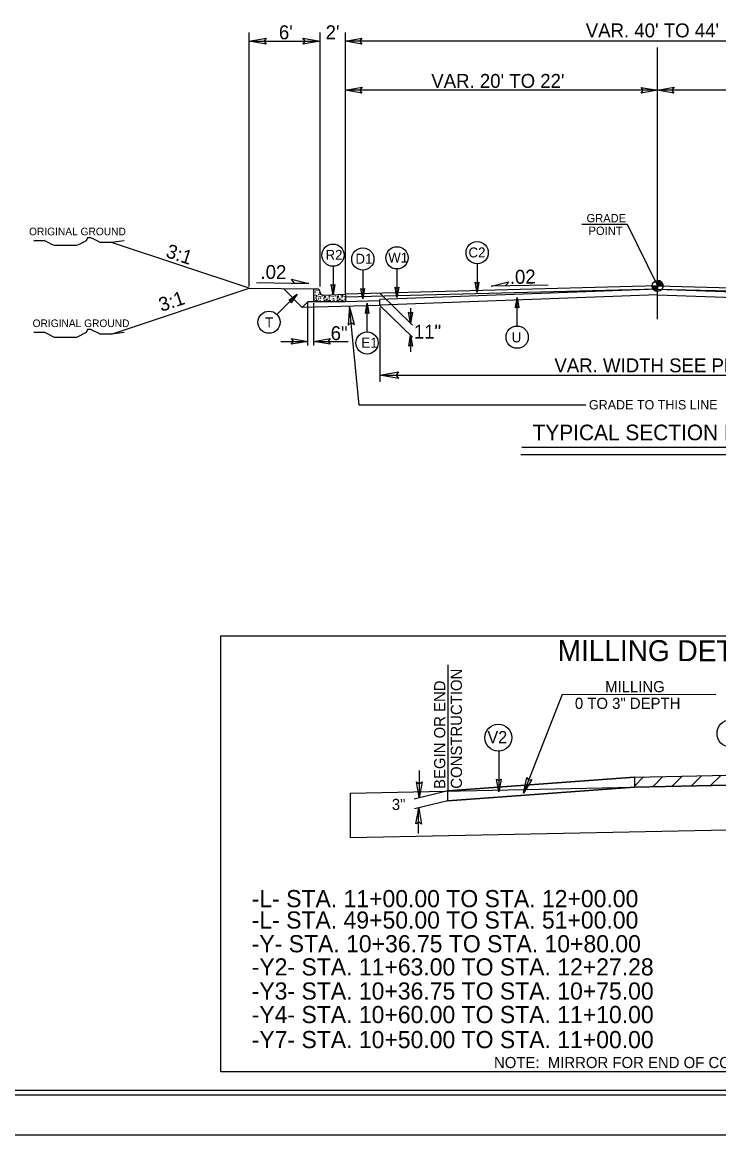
# Model space of a CAD drawing. Extents: x 957297 to 961629, y 830661 to 840840.
# Drawn here: x 959081 to 959472, y 830661 to 831285 of the extents above; entities that cross this region are included whole.
import ezdxf

# ---------------------------------------------------------------- set-up
doc = ezdxf.new("R2010")
doc.units = 0
for name, color, linetype in [('Default', 7, 'Continuous'), ('Old_Level_1', 7, 'Continuous'), ('Old_Level_11', 7, 'Continuous'), ('Old_Level_21', 7, 'Continuous'), ('Old_Level_3', 7, 'Continuous'), ('Prop Dimension', 7, 'Continuous'), ('Prop Dimension Text', 7, 'Continuous'), ('Sheet Plot Border Inside CELL', 7, 'Continuous'), ('Sheet Plot Border Outside CELL', 7, 'Continuous'), ('Sheet Typical CELL', 7, 'Continuous'), ('Typical ID Circle CELL', 7, 'Continuous'), ('Typical Pavement Slope CELL', 7, 'Continuous'), ('Typical Terminator CELL', 7, 'Continuous'), ('Typical Text Grade Point CELL', 7, 'Continuous'), ('Typical Text ID Circle CELL', 7, 'Continuous')]:
    doc.layers.add(name, color=color, linetype=linetype)

msp = doc.modelspace()

# ---------------------------------------------------------------- linework, layer by layer
at = {"layer": 'Default'}
msp.add_line((959437.72, 831118.14), (959437.72, 831270.38), dxfattribs=at)
at = {"layer": 'Old_Level_1'}
for p, q in [((959208.65, 831136.31), (959208.65, 831278.82)), ((959248.48, 831136.31), (959248.48, 831278.82)), ((959262.72, 831132.16), (959262.72, 831278.82)), ((959208.65, 831273.95), (959248.48, 831273.95)), ((959612.72, 831273.95), (959262.72, 831273.95)), ((959437.72, 831246.46), (959262.72, 831246.46)), ((959612.72, 831246.46), (959437.72, 831246.46)), ((959208.65, 831135.37), (959131.47, 831161.1)), ((959212.89, 831138.59), (959242.11, 831138)), ((959437.72, 831136.71), (959437.72, 831139.78)), ((959131.47, 831109.64), (959208.65, 831135.37)), ((959208.65, 831135.37), (959244.92, 831135.01)), ((959238.5, 831124.7), (959228.03, 831135.18)), ((959437.72, 831136.71), (959262.72, 831132.16)), ((959437.72, 831134.98), (959262.72, 831130.43)), ((959437.72, 831134.98), (959281.92, 831129.06)), ((959281.92, 831132.66), (959300.39, 831114.73)), ((959437.68, 831131.79), (959281.92, 831125.88)), ((959376.37, 831137.18), (959344.4, 831136.54)), ((959434.66, 831136.71), (959437.72, 831136.71)), ((959437.68, 831131.79), (959593.52, 831125.87)), ((959437.72, 831136.71), (959612.72, 831132.16)), ((959440.78, 831136.71), (959437.72, 831136.71)), ((959437.72, 831133.66), (959437.72, 831136.71)), ((959437.72, 831136.71), (959437.72, 831133.66)), ((959437.72, 831136.71), (959437.72, 831134.98)), ((959437.72, 831134.98), (959612.72, 831130.43)), ((959437.72, 831134.98), (959593.52, 831129.06)), ((959241.62, 831127.82), (959238.5, 831124.7)), ((959281.92, 831125.83), (959238.5, 831124.7)), ((959244.92, 831127.88), (959241.62, 831127.82)), ((959241.62, 831103.33), (959241.62, 831127.37)), ((959244.92, 831103.33), (959244.92, 831127.08)), ((959281.92, 831128.38), (959262.72, 831127.88)), ((959270.46, 831069.9), (959264.98, 831125.39)), ((959281.92, 831125.88), (959281.92, 831129.06)), ((959281.92, 831125.83), (959281.92, 831125.88)), ((959281.92, 831125.83), (959300.39, 831107.9)), ((959281.92, 831124.68), (959281.92, 831083.02)), ((959299.18, 831124.26), (959299.18, 831115.9)), ((959299.25, 831109.01), (959299.25, 831099.79)), ((959226.42, 831105.62), (959241.62, 831105.62)), ((959244.92, 831105.62), (959264.18, 831105.62)), ((959281.92, 831086.71), (959593.52, 831086.71)), ((959397.52, 831069.9), (959270.46, 831069.9)), ((959361.6, 831046.32), (959529.29, 831046.32)), ((959361.04, 831042.2), (959528.74, 831042.2)), ((959424.73, 830856.17), (959429.87, 830861.32)), ((959435.01, 830855.85), (959440.7, 830861.54)), ((959445.84, 830856.07), (959451.53, 830861.77)), ((959456.67, 830856.3), (959462.37, 830861.99)), ((959467.5, 830856.52), (959473.2, 830862.22))]:
    msp.add_line(p, q, dxfattribs=at)
for points in [[(959437.76, 831139.78), (959437.76, 831139.78), (959437.76, 831136.71)], [(959437.81, 831139.78), (959437.81, 831136.71)], [(959437.87, 831139.77), (959437.87, 831136.71)], [(959437.94, 831139.76), (959437.94, 831136.71)], [(959438, 831139.76), (959438, 831136.71)], [(959438.06, 831139.76), (959438.06, 831136.71)], [(959438.12, 831139.75), (959438.12, 831136.71)], [(959438.18, 831139.75), (959438.18, 831136.71)], [(959438.23, 831139.72), (959438.23, 831136.71)], [(959438.3, 831139.72), (959438.3, 831136.71)], [(959438.36, 831139.71), (959438.36, 831136.71)], [(959438.42, 831139.69), (959438.42, 831136.71)], [(959438.49, 831139.67), (959438.49, 831136.71)], [(959438.55, 831139.66), (959438.55, 831136.71)], [(959438.61, 831139.64), (959438.61, 831136.71)], [(959438.67, 831139.62), (959438.67, 831136.71)], [(959438.74, 831139.6), (959438.73, 831136.71)], [(959438.79, 831139.58), (959438.79, 831136.71)], [(959438.85, 831139.56), (959438.85, 831136.71)], [(959438.92, 831139.53), (959438.92, 831136.71)], [(959438.98, 831139.51), (959438.98, 831136.71)], [(959439.04, 831139.47), (959439.04, 831136.71)], [(959439.09, 831139.45), (959439.09, 831136.71)], [(959439.15, 831139.43), (959439.15, 831136.71)], [(959439.21, 831139.39), (959439.21, 831136.71)], [(959439.28, 831139.35), (959439.28, 831136.71)], [(959439.34, 831139.31), (959439.34, 831136.71)], [(959439.4, 831139.27), (959439.4, 831136.71)], [(959439.47, 831139.22), (959439.47, 831136.71)], [(959439.52, 831139.19), (959439.52, 831136.71)], [(959439.59, 831139.14), (959439.59, 831136.71)], [(959439.65, 831139.09), (959439.65, 831136.71)], [(959439.71, 831139.05), (959439.71, 831136.71)], [(959439.77, 831138.99), (959439.77, 831136.71)], [(959439.83, 831138.93), (959439.83, 831136.71)], [(959439.9, 831138.87), (959439.9, 831136.71)], [(959439.95, 831138.8), (959439.95, 831136.71)], [(959440.01, 831138.74), (959440.01, 831136.71)], [(959440.07, 831138.68), (959440.07, 831136.71)], [(959440.13, 831138.58), (959440.13, 831136.71)], [(959440.2, 831138.51), (959440.2, 831136.71)], [(959440.26, 831138.43), (959440.26, 831136.71)], [(959440.32, 831138.33), (959440.32, 831136.71)], [(959440.38, 831138.23), (959440.38, 831136.71)], [(959440.44, 831138.12), (959440.44, 831136.71)], [(959440.5, 831137.98), (959440.5, 831136.71)], [(959440.57, 831137.83), (959440.57, 831136.71)], [(959440.63, 831137.67), (959440.63, 831136.71)], [(959440.69, 831137.46), (959440.69, 831136.71)], [(959434.68, 831136.71), (959434.68, 831136.39)], [(959434.74, 831136.71), (959434.74, 831136.03)], [(959434.8, 831136.71), (959434.8, 831135.8)], [(959434.86, 831136.71), (959434.86, 831135.62)], [(959434.93, 831136.71), (959434.93, 831135.48)], [(959434.99, 831136.71), (959434.99, 831135.35)], [(959435.05, 831136.71), (959435.05, 831135.24)], [(959435.11, 831136.71), (959435.11, 831135.12)], [(959435.17, 831136.71), (959435.17, 831135.04)], [(959435.23, 831136.71), (959435.23, 831134.95)], [(959435.3, 831136.71), (959435.3, 831134.86)], [(959435.36, 831136.71), (959435.36, 831134.79)], [(959435.42, 831136.71), (959435.42, 831134.72)], [(959435.47, 831136.71), (959435.47, 831134.64)], [(959435.53, 831136.71), (959435.53, 831134.57)], [(959435.6, 831136.71), (959435.6, 831134.52)], [(959435.66, 831136.71), (959435.66, 831134.47)], [(959435.72, 831136.71), (959435.72, 831134.41)], [(959435.78, 831136.71), (959435.78, 831134.36)], [(959435.85, 831136.71), (959435.85, 831134.3)], [(959435.9, 831136.71), (959435.9, 831134.26)], [(959435.96, 831136.71), (959435.96, 831134.22)], [(959436.02, 831136.71), (959436.02, 831134.18)], [(959436.09, 831136.71), (959436.09, 831134.13)], [(959436.15, 831136.71), (959436.15, 831134.09)], [(959436.21, 831136.71), (959436.21, 831134.05)], [(959436.28, 831136.71), (959436.28, 831134.02)], [(959436.33, 831136.71), (959436.33, 831134)], [(959436.39, 831136.71), (959436.39, 831133.97)], [(959436.46, 831136.71), (959436.46, 831133.93)], [(959436.52, 831136.71), (959436.52, 831133.91)], [(959436.58, 831136.71), (959436.58, 831133.88)], [(959436.64, 831136.71), (959436.64, 831133.86)], [(959436.7, 831136.71), (959436.7, 831133.84)], [(959436.75, 831136.71), (959436.75, 831133.82)], [(959436.82, 831136.71), (959436.82, 831133.8)], [(959436.88, 831136.71), (959436.88, 831133.78)], [(959436.94, 831136.71), (959436.94, 831133.76)], [(959437, 831136.71), (959437, 831133.75)], [(959437.07, 831136.71), (959437.07, 831133.73)], [(959437.13, 831136.71), (959437.13, 831133.72)], [(959437.19, 831136.71), (959437.19, 831133.72)], [(959437.25, 831136.71), (959437.25, 831133.7)], [(959437.31, 831136.71), (959437.31, 831133.68)], [(959437.38, 831136.71), (959437.38, 831133.68)], [(959437.44, 831136.71), (959437.44, 831133.68)], [(959437.5, 831136.71), (959437.5, 831133.66)], [(959437.56, 831136.71), (959437.56, 831133.66)], [(959437.61, 831136.71), (959437.61, 831133.66)], [(959437.67, 831136.71), (959437.67, 831133.66), (959437.67, 831133.66)], [(959440.75, 831137.16), (959440.75, 831136.71)]]:
    msp.add_lwpolyline(points, dxfattribs=at)
for points in [[(959192.77, 830940.53), (959740.5, 830940.53), (959740.5, 830695.87), (959192.77, 830695.87)], [(959320.22, 830853.46), (959424.71, 830861.21), (959424.73, 830855.63), (959320.22, 830847.89)]]:
    msp.add_lwpolyline(points, close=True, dxfattribs=at)
msp.add_circle((959437.72, 831136.72), 3.06, dxfattribs=at)
for start, end in [(359.99048, 89.99048), (179.99048, 269.99048)]:
    msp.add_arc((959437.72, 831136.72), 3.06, start, end, dxfattribs=at)
at = {"layer": 'Old_Level_11'}
for p, q in [((959234.11, 831138.16), (959232.38, 831140.42)), ((959232.38, 831140.42), (959242.11, 831138)), ((959242.11, 831138), (959234.11, 831138.16)), ((959344.4, 831136.54), (959354.15, 831138.96)), ((959354.15, 831138.96), (959352.42, 831136.7)), ((959352.42, 831136.7), (959344.4, 831136.54))]:
    msp.add_line(p, q, dxfattribs=at)
for points in [[(959218.26, 831272.3), (959208.65, 831273.95), (959218.31, 831275.66), (959217.09, 831273.95)], [(959238.87, 831275.61), (959248.48, 831273.95), (959238.81, 831272.23), (959240.04, 831273.95)], [(959267.84, 831115.05), (959264.98, 831125.39), (959264.16, 831114.63), (959265.89, 831116.15)], [(959292.49, 831084.89), (959281.92, 831086.71), (959292.55, 831088.59), (959291.2, 831086.71)]]:
    msp.add_lwpolyline(points, close=True, dxfattribs=at)
at = {"layer": 'Old_Level_21'}
for points in [[(959138.56, 831161.98), (959131.47, 831161.1), (959129.69, 831161.1), (959127.03, 831161.1), (959125.26, 831161.1), (959123.49, 831161.98), (959121.71, 831162.88), (959119.94, 831163.76), (959118.16, 831163.76), (959117.27, 831161.98), (959115.5, 831161.1), (959113.73, 831160.21), (959111.96, 831159.33), (959110.18, 831159.33), (959108.41, 831159.33), (959106.63, 831159.33), (959104.86, 831159.33), (959103.09, 831159.33), (959101.32, 831159.33), (959099.54, 831159.33), (959097.77, 831160.21), (959096, 831161.1), (959094.23, 831161.98), (959091.56, 831161.98), (959089.79, 831161.98), (959088.01, 831161.98)], [(959138.56, 831110.52), (959131.47, 831109.64), (959129.69, 831109.64), (959127.03, 831109.64), (959125.26, 831109.64), (959123.49, 831110.52), (959121.71, 831111.42), (959119.94, 831112.3), (959118.16, 831112.3), (959117.27, 831110.52), (959115.5, 831109.64), (959113.73, 831108.74), (959111.96, 831107.87), (959110.18, 831107.87), (959108.41, 831107.87), (959106.63, 831107.87), (959104.86, 831107.87), (959103.09, 831107.87), (959101.32, 831107.87), (959099.54, 831107.87), (959097.77, 831108.74), (959096, 831109.64), (959094.23, 831110.52), (959091.56, 831110.52), (959089.79, 831110.52), (959088.01, 831110.52)]]:
    msp.add_lwpolyline(points, dxfattribs=at)
at = {"layer": 'Old_Level_3'}
for p, q in [((959244.92, 831131.44), (959244.92, 831134.7)), ((959244.92, 831127.88), (959244.92, 831131.44)), ((959245.23, 831135.01), (959246.7, 831135.01)), ((959246.28, 831131.19), (959246.28, 831130.57)), ((959246.91, 831131.16), (959246.28, 831131.19)), ((959246.28, 831130.57), (959246.91, 831131.16)), ((959248.62, 831132.81), (959248.5, 831132.65)), ((959248.5, 831132.65), (959248.66, 831132.69)), ((959250.32, 831131.54), (959262.72, 831132.16)), ((959250.32, 831131.54), (959250.32, 831131.54)), ((959253.51, 831131.19), (959253.51, 831130.57)), ((959254.14, 831131.16), (959253.51, 831131.19)), ((959253.51, 831130.57), (959254.14, 831131.16)), ((959260.74, 831131.19), (959260.74, 831130.57)), ((959261.37, 831131.16), (959260.74, 831131.19)), ((959260.74, 831130.57), (959261.37, 831131.16)), ((959262.72, 831132.16), (959262.72, 831127.88)), ((959262.72, 831127.88), (959244.92, 831127.88)), ((959246.19, 831128.29), (959246.69, 831128.99)), ((959246.88, 831128.33), (959246.19, 831128.29)), ((959246.69, 831128.99), (959246.88, 831128.33)), ((959250.61, 831128), (959250.98, 831128.66)), ((959251.58, 831128.23), (959250.61, 831128)), ((959250.82, 831130.76), (959250.92, 831130.24)), ((959251.71, 831130.51), (959250.82, 831130.76)), ((959250.92, 831130.24), (959251.71, 831130.51)), ((959250.98, 831128.66), (959251.58, 831128.23)), ((959253.42, 831128.29), (959253.92, 831128.99)), ((959254.11, 831128.33), (959253.42, 831128.29)), ((959253.92, 831128.99), (959254.11, 831128.33)), ((959257.84, 831128), (959258.21, 831128.66)), ((959258.81, 831128.23), (959257.84, 831128)), ((959258.04, 831130.76), (959258.15, 831130.24)), ((959258.94, 831130.51), (959258.04, 831130.76)), ((959258.15, 831130.24), (959258.94, 831130.51)), ((959258.21, 831128.66), (959258.81, 831128.23)), ((959260.65, 831128.29), (959261.14, 831128.99)), ((959261.34, 831128.33), (959260.65, 831128.29)), ((959261.14, 831128.99), (959261.34, 831128.33))]:
    msp.add_line(p, q, dxfattribs=at)
for centre in [(959244.98, 831133.15), (959245.66, 831131.66), (959245.79, 831133.05), (959245.96, 831133.84), (959246.88, 831134.24), (959247.05, 831133.25), (959247.74, 831131.86), (959248.07, 831134.1), (959248.11, 831132.72), (959248.93, 831131.82), (959249.99, 831131.16), (959251.54, 831131), (959257.22, 831131.16), (959258.77, 831131), (959260.12, 831131.66), (959262.2, 831131.86), (959245.08, 831130.37), (959245.11, 831128.03), (959245.2, 831129.22), (959245.66, 831128.3), (959245.83, 831129.94), (959246.39, 831129.45), (959246.65, 831130.04), (959247.51, 831129.68), (959247.68, 831129.09), (959248.04, 831130.67), (959248.54, 831128.59), (959248.7, 831129.59), (959248.8, 831129.88), (959248.83, 831130.73), (959249.26, 831128.76), (959250.29, 831129.71), (959250.98, 831129.42), (959252.01, 831128.86), (959252.11, 831129.42), (959252.3, 831130.37), (959252.34, 831128.03), (959252.43, 831129.22), (959252.89, 831128.3), (959253.06, 831129.94), (959253.62, 831129.45), (959253.88, 831130.04), (959254.74, 831129.68), (959254.91, 831129.09), (959255.27, 831130.67), (959255.76, 831128.59), (959255.93, 831129.59), (959256.03, 831129.88), (959256.06, 831130.73), (959256.49, 831128.76), (959257.52, 831129.71), (959258.21, 831129.42), (959259.23, 831128.86), (959259.33, 831129.42), (959259.53, 831130.37), (959259.56, 831128.03), (959259.65, 831129.22), (959260.12, 831128.3), (959260.28, 831129.94), (959260.84, 831129.45), (959261.11, 831130.04), (959261.97, 831129.68), (959262.13, 831129.09), (959262.5, 831130.67)]:
    msp.add_circle(centre, 0.0464, dxfattribs=at)
for centre, radius, start, end in [((959245.23, 831134.7), 0.309, 90, 180), ((959245.11, 831134.93), 0.0464, 259.65309, 10.34691), ((959246.7, 831133.23), 1.78, 1.07335, 90), ((959250.23, 831133.3), 1.76, 181.07335, 272.86241), ((959252.89, 831131.66), 0.0464, 167.77954, 17.93798), ((959256.16, 831131.82), 0.0464, 169.83737, 15.88014), ((959244.88, 831129.42), 0.0464, 330.41727, 29.58272)]:
    msp.add_arc(centre, radius, start, end, dxfattribs=at)
at = {"layer": 'Prop Dimension'}
for p, q in [((959320.22, 830924.12), (959320.22, 830853.46)), ((959304.13, 830864.89), (959304.13, 830849.64)), ((959320.22, 830853.46), (959301.23, 830848.95)), ((959320.22, 830847.89), (959301.43, 830843.44)), ((959303.72, 830829.69), (959303.72, 830843.98))]:
    msp.add_line(p, q, dxfattribs=at)
msp.add_lwpolyline([(959470.35, 830907.4), (959384.28, 830907.52), (959362.58, 830852.23)], dxfattribs=at)
at = {"layer": 'Sheet Plot Border Inside CELL'}
msp.add_lwpolyline([(960390.3, 831738.21), (958723.8, 831738.21), (958723.8, 830683.11), (960390.3, 830683.11)], close=True, dxfattribs=at)
at = {"layer": 'Sheet Plot Border Outside CELL'}
msp.add_lwpolyline([(960394.8, 831760.66), (958710.8, 831760.66), (958710.8, 830660.66), (960394.8, 830660.66)], close=True, dxfattribs=at)
at = {"layer": 'Sheet Typical CELL'}
msp.add_lwpolyline([(960377.8, 831735.66), (958877.8, 831735.66), (958877.8, 830685.66), (960377.8, 830685.66)], close=True, dxfattribs=at)
at = {"layer": 'Typical ID Circle CELL'}
for p, q in [((959255.75, 831147.76), (959255.75, 831131.68)), ((959272.45, 831145.58), (959272.45, 831129.49)), ((959291.58, 831146.26), (959291.58, 831130.17)), ((959336.57, 831149.11), (959336.57, 831133.02)), ((959224.28, 831120.76), (959235.66, 831132.13)), ((959274.86, 831110.95), (959274.86, 831127.04)), ((959358.98, 831114.19), (959358.98, 831130.28))]:
    msp.add_line(p, q, dxfattribs=at)
msp.add_lwpolyline([(959348.79, 830875.76), (959348.79, 830854.54)], dxfattribs=at)
msp.add_lwpolyline([(959350.02, 830860.12), (959348.78, 830852.97), (959347.51, 830860.16), (959348.78, 830859.25)], close=True, dxfattribs=at)
for centre, radius in [((959255.75, 831153.99), 6.23), ((959272.45, 831151.8), 6.23), ((959291.58, 831152.48), 6.23), ((959336.57, 831155.33), 6.23), ((959219.88, 831116.36), 6.23), ((959358.98, 831107.97), 6.23), ((959274.86, 831104.73), 6.23), ((959348.42, 830883.36), 7.6), ((959478.66, 830885.71), 7.6)]:
    msp.add_circle(centre, radius, dxfattribs=at)
at = {"layer": 'Typical Pavement Slope CELL'}
for p, q in [((959424.71, 830861.21), (959568.1, 830864.19)), ((959265.6, 830852.33), (959568.1, 830858.61)), ((959424.71, 830861.21), (959320.22, 830853.46)), ((959568.1, 830858.61), (959424.73, 830855.63)), ((959265.48, 830827.23), (959265.6, 830852.33)), ((959320.22, 830847.89), (959424.73, 830855.63)), ((959320.22, 830847.89), (959424.73, 830855.63)), ((959424.73, 830855.63), (959320.22, 830847.89)), ((959265.57, 830827.33), (959568.62, 830833.63))]:
    msp.add_line(p, q, dxfattribs=at)
at = {"layer": 'Typical Terminator CELL'}
for points in [[(959271.94, 831272.36), (959262.72, 831273.95), (959271.99, 831275.59), (959270.81, 831273.95)], [(959271.94, 831244.87), (959262.72, 831246.46), (959272, 831248.1), (959270.82, 831246.46)], [(959428.5, 831248.05), (959437.72, 831246.46), (959428.45, 831244.82), (959429.63, 831246.46)], [(959446.94, 831244.87), (959437.72, 831246.46), (959446.99, 831248.1), (959445.81, 831246.46)], [(959256.74, 831137.44), (959255.75, 831131.68), (959254.73, 831137.47), (959255.75, 831136.74)], [(959337.56, 831138.78), (959336.57, 831133.02), (959335.54, 831138.81), (959336.57, 831138.08)], [(959230.88, 831128.76), (959235.66, 831132.13), (959232.28, 831127.31), (959232.08, 831128.56)], [(959273.44, 831135.25), (959272.45, 831129.49), (959271.43, 831135.29), (959272.45, 831134.55)], [(959292.57, 831135.93), (959291.58, 831130.17), (959290.55, 831135.96), (959291.58, 831135.23)], [(959273.87, 831121.28), (959274.86, 831127.04), (959275.89, 831121.24), (959274.86, 831121.98)], [(959357.99, 831124.52), (959358.98, 831130.28), (959360, 831124.49), (959358.98, 831125.22)], [(959300.23, 831121.97), (959299.18, 831115.9), (959298.1, 831122), (959299.18, 831121.23)], [(959232.39, 831107.21), (959241.62, 831105.62), (959232.34, 831103.98), (959233.52, 831105.62)], [(959254.14, 831104.03), (959244.92, 831105.62), (959254.19, 831107.26), (959253.01, 831105.62)], [(959298.2, 831102.94), (959299.25, 831109.01), (959300.32, 831102.91), (959299.25, 831103.68)], [(959305.66, 830858.52), (959304.13, 830849.64), (959302.55, 830858.56), (959304.13, 830857.43)], [(959367.25, 830859.93), (959362.58, 830852.23), (959364.37, 830861.11), (959365.43, 830859.48)], [(959302.25, 830834.95), (959303.78, 830843.82), (959305.36, 830834.9), (959303.78, 830836.03)]]:
    msp.add_lwpolyline(points, close=True, dxfattribs=at)
at = {"layer": 'Typical Text Grade Point CELL'}
for p, q in [((959395.28, 831171.27), (959420.61, 831171.27)), ((959420.61, 831171.27), (959437.72, 831136.71))]:
    msp.add_line(p, q, dxfattribs=at)

# ---------------------------------------------------------------- texts
at = {"layer": 'Default'}
msp.add_text('MILLING DETAIL', height=11.739, rotation=359.94689, dxfattribs=at).set_placement((959381.74, 830926.34))
for s, p in [('-L- STA. 11+00.00 TO STA. 12+00.00', (959210.17, 830788.28)), ('-L- STA. 49+50.00 TO STA. 51+00.00', (959210.17, 830776.28)), ('-Y- STA. 10+36.75 TO STA. 10+80.00', (959210.17, 830762.98)), ('-Y2- STA. 11+63.00 TO STA. 12+27.28', (959210.17, 830749.99)), ('-Y3- STA. 10+36.75 TO STA. 10+75.00', (959210.17, 830736.47)), ('-Y4- STA. 10+60.00 TO STA. 11+10.00', (959210.17, 830723.28)), ('-Y7- STA. 10+50.00 TO STA. 11+00.00', (959210.17, 830709.23))]:
    msp.add_text(s, height=9.6251, dxfattribs=at).set_placement(p)
at = {"layer": 'Old_Level_1'}
for s, height, p in [("VAR. 40' TO 44'", 7.8009, (959397.46, 831276.13)), ("VAR. 20' TO 22'", 7.8009, (959310.84, 831247.79)), ('VAR. WIDTH SEE PLANS', 7.8009, (959379.89, 831088.27)), ('GRADE TO THIS LINE', 5.2473, (959399.24, 831067.45)), ('TYPICAL SECTION NO. 20', 8.7513, (959367.65, 831050.17))]:
    msp.add_text(s, height=height, dxfattribs=at).set_placement(p)
at = {"layer": 'Old_Level_11'}
for s, height, p in [('GRADE', 4.671, (959397.89, 831172.39)), ('POINT', 4.671, (959399.02, 831165.32)), ('11"', 7.801, (959301.06, 831107.14))]:
    msp.add_text(s, height=height, dxfattribs=at).set_placement(p)
at = {"layer": 'Old_Level_21'}
for p in [(959085.31, 831165.1), (959087.3, 831113.63)]:
    msp.add_text('ORIGINAL GROUND', height=4.2722, dxfattribs=at).set_placement(p)
at = {"layer": 'Old_Level_3'}
for s, p in [("6'", (959225.4, 831275.06)), ("2'", (959251.6, 831275.06))]:
    msp.add_text(s, height=7.801, dxfattribs=at).set_placement(p)
for s, rotation, p in [('3:1', 341.56515, (959161.5, 831153.07)), ('.02', 359.43356, (959215.03, 831140.69)), ('3:1', 18.43485, (959159.53, 831122.15))]:
    msp.add_text(s, height=7.801, rotation=rotation, dxfattribs=at).set_placement(p)
at = {"layer": 'Prop Dimension Text'}
for s, height, rotation, p in [('.02', 7.801, 1.18394, (959354.97, 831137.81)), ('6"', 7.801, 0, (959254.42, 831106.33)), ('CONSTRUCTION', 6.25, 89.99999, (959328.05, 830854.73)), ('BEGIN OR END', 6.25, 89.99999, (959318.68, 830854.62)), ('MILLING', 6.25, 359.99999, (959408.31, 830908.86)), ('0 TO 3" DEPTH', 6.25, 359.99999, (959391.37, 830899.49)), ('3"', 6.25, 359.99999, (959288.74, 830842.8)), ('NOTE:  MIRROR FOR END OF CONSTRUCTION', 6.25, 359.99999, (959346.01, 830698.05))]:
    msp.add_text(s, height=height, rotation=rotation, dxfattribs=at).set_placement(p)
at = {"layer": 'Typical Text ID Circle CELL'}
for s, height, p in [('R2', 5.572, (959251.55, 831151.36)), ('C2', 5.572, (959331.7, 831152.7)), ('D1', 5.572, (959268.31, 831149.17)), ('W1', 5.572, (959286.7, 831149.85)), ('E1', 5.572, (959271.65, 831102.09)), ('U', 5.57, (959355.95, 831105.03)), ('V2', 6.79, (959342.32, 830880.27))]:
    msp.add_text(s, height=height, dxfattribs=at).set_placement(p)
msp.add_text('T', height=5.57, rotation=360, dxfattribs=at).set_placement((959217.7, 831113.48))

doc.saveas('drawing.dxf')
